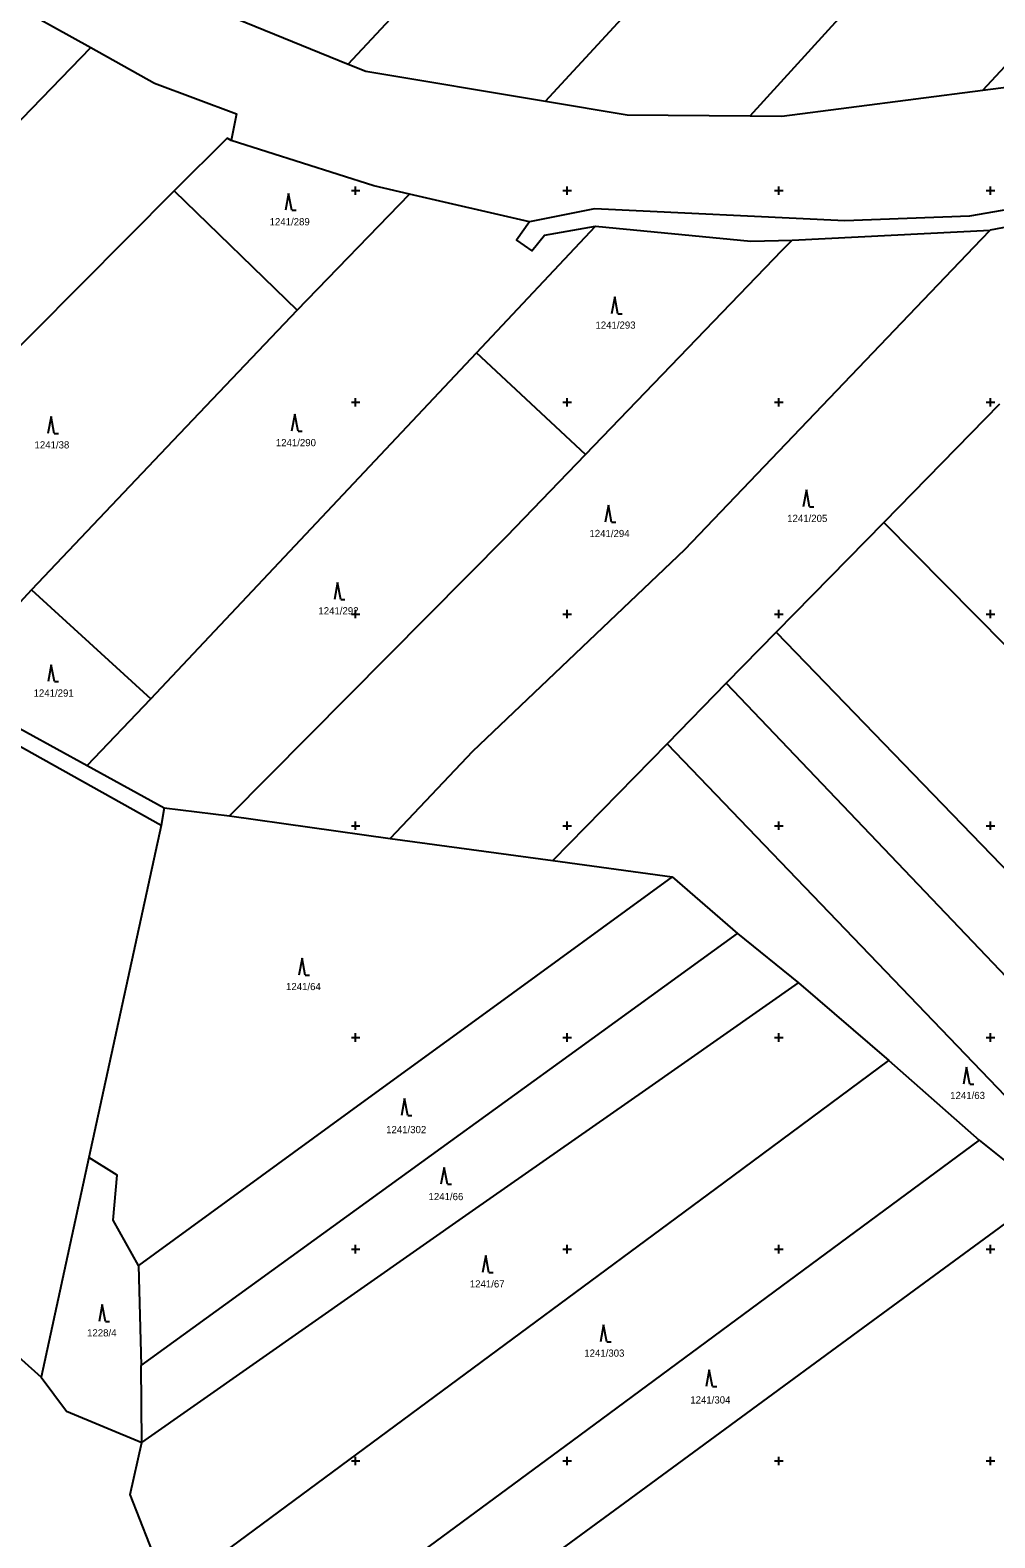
# Model space of a CAD drawing. Extents: x -776734 to -748832, y -1118122 to -976986.
# Drawn here: x -751976.9 to -751749, y -1115218.2 to -1114862.1 of the extents above; entities that cross this region are included whole.
import ezdxf

# ---------------------------------------------------------------- set-up
doc = ezdxf.new("R2010")
doc.units = 0
for name, color, linetype in [('KM_Hranice obce', 7, 'Continuous'), ('KM_Hranice parcel', 7, 'Continuous'), ('KM_Parcelní čísla', 7, 'Continuous'), ('KM_Značky kultur', 7, 'Continuous'), ('Level 61 Křížky', 7, 'Continuous')]:
    doc.layers.add(name, color=color, linetype=linetype)

msp = doc.modelspace()

# ---------------------------------------------------------------- linework, layer by layer
at = {"layer": 'KM_Hranice obce'}
for p, q in [((-751997.63, -1115016.98), (-751963.38, -1115035.78)), ((-751997.63, -1115016.98), (-751963.38, -1115035.78)), ((-751963.38, -1115035.78), (-751945.21, -1115045.76)), ((-751963.38, -1115035.78), (-751945.21, -1115045.76)), ((-751945.21, -1115045.76), (-751945.91, -1115049.96)), ((-751945.21, -1115045.76), (-751945.91, -1115049.96)), ((-751945.91, -1115049.96), (-751963.05, -1115128.37)), ((-751945.91, -1115049.96), (-751963.05, -1115128.37)), ((-751963.05, -1115128.37), (-751974.26, -1115180.24)), ((-751963.05, -1115128.37), (-751974.26, -1115180.24))]:
    msp.add_line(p, q, dxfattribs=at)
for points in [[(-751974.26, -1115180.24), (-751968.3, -1115188.26), (-751950.49, -1115195.65)], [(-751974.26, -1115180.24), (-751968.3, -1115188.26), (-751950.49, -1115195.65)], [(-751944.08, -1115231.19), (-751953.23, -1115207.95), (-751950.49, -1115195.65)], [(-751944.08, -1115231.19), (-751953.23, -1115207.95), (-751950.49, -1115195.65)]]:
    msp.add_lwpolyline(points, dxfattribs=at)
at = {"layer": 'KM_Hranice parcel'}
for p, q in [((-751939.11, -1114854.9), (-751901.76, -1114870.11)), ((-751942.86, -1114900.08), (-751913.81, -1114928.23)), ((-751913.81, -1114928.23), (-751887.29, -1114900.81)), ((-751858.89, -1114907.41), (-751887.29, -1114900.81)), ((-751871.43, -1114938.34), (-751843.29, -1114908.38)), ((-751796.89, -1114911.7), (-751750.07, -1114909.36)), ((-751845.67, -1114962.32), (-751871.43, -1114938.34)), ((-751747.89, -1114950.46), (-751775.23, -1114978.37)), ((-751775.23, -1114978.37), (-751800.61, -1115004.27)), ((-751976.59, -1114994.29), (-751997.63, -1115016.98)), ((-751976.59, -1114994.29), (-751948.36, -1115020.01)), ((-751800.61, -1115004.27), (-751812.42, -1115016.33)), ((-751812.42, -1115016.33), (-751826.42, -1115030.62)), ((-751963.38, -1115035.78), (-751948.36, -1115020.01)), ((-751826.42, -1115030.62), (-751853.43, -1115058.19)), ((-751945.21, -1115045.76), (-751929.77, -1115047.62)), ((-751929.77, -1115047.62), (-751891.86, -1115053)), ((-751891.86, -1115053), (-751853.43, -1115058.19)), ((-751853.43, -1115058.19), (-751825.21, -1115062.03)), ((-751825.21, -1115062.03), (-751809.77, -1115075.48)), ((-751809.77, -1115075.48), (-751795.37, -1115087.1)), ((-751795.37, -1115087.1), (-751774.05, -1115105.47)), ((-751774.05, -1115105.47), (-751752.68, -1115124.23)), ((-751752.68, -1115124.23), (-751736.94, -1115136.91)), ((-751950.49, -1115195.65), (-751872.35, -1115140.97)), ((-751951.27, -1115153.86), (-751950.66, -1115177.43)), ((-751950.49, -1115195.65), (-751950.66, -1115177.43))]:
    msp.add_line(p, q, dxfattribs=at)
for points in [[(-751901.76, -1114870.11), (-751882.74, -1114849.78), (-751856.57, -1114821.81), (-751816.46, -1114778.95), (-751734.46, -1114691.3), (-751678.34, -1114631.33), (-751649.12, -1114600.1), (-751642.03, -1114593.16)], [(-751855.14, -1114878.92), (-751824.7, -1114845.88), (-751783.59, -1114801.27), (-751766.66, -1114782.9), (-751738.11, -1114751.92), (-751722.27, -1114734.73), (-751704.16, -1114715.09), (-751657.73, -1114664.7), (-751615.2, -1114618.55), (-751610.82, -1114613.8)], [(-751806.78, -1114882.34), (-751721.42, -1114788.59), (-751667.32, -1114729.17), (-751615.76, -1114672.55), (-751613.29, -1114669.83)], [(-751751.78, -1114876.29), (-751714.18, -1114835.71), (-751676.85, -1114795.4), (-751615.92, -1114729.62)], [(-751995.98, -1114846.36), (-751983.87, -1114854.34), (-751962.52, -1114866.24)], [(-752071.79, -1114978.8), (-752018.24, -1114923.64), (-751962.52, -1114866.24)], [(-751962.52, -1114866.24), (-751947.48, -1114874.63), (-751928.13, -1114881.84), (-751929.4, -1114888.2)], [(-751619.58, -1114864.94), (-751671.94, -1114882.94), (-751717.81, -1114899.58), (-751754.97, -1114906.02), (-751784.43, -1114907.15), (-751843.55, -1114904.34), (-751858.89, -1114907.41)], [(-751751.78, -1114876.29), (-751711.61, -1114871.13), (-751698.88, -1114867.14)], [(-751901.76, -1114870.11), (-751897.6, -1114871.8), (-751855.14, -1114878.92)], [(-751806.78, -1114882.34), (-751799.31, -1114882.39), (-751751.78, -1114876.29)], [(-751855.14, -1114878.92), (-751835.87, -1114882.14), (-751806.78, -1114882.34)], [(-751929.4, -1114888.2), (-751930.34, -1114887.63), (-751942.86, -1114900.08)], [(-751887.29, -1114900.81), (-751895.7, -1114898.86), (-751929.4, -1114888.2)], [(-751694.2, -1114895.66), (-751707.54, -1114900.39), (-751716.28, -1114908.3), (-751720.75, -1114906.52), (-751718.97, -1114903.41), (-751750.07, -1114909.36)], [(-751942.86, -1114900.08), (-751987.35, -1114944.76), (-752031.68, -1114989.28)], [(-751945.91, -1115049.96), (-752018.39, -1115009.46), (-752037.33, -1114987.77), (-752047.6, -1114984.5), (-752062, -1114982.88), (-752081.53, -1114981.75), (-752107.58, -1114982.78), (-752126.36, -1114977.53), (-752161.17, -1114970.24), (-752199.76, -1114966.35), (-752226.58, -1114956.72), (-752268.96, -1114949.99), (-752281.26, -1114938.54), (-752287.32, -1114936.37), (-752294.09, -1114925.53), (-752295.5, -1114906.88)], [(-751750.07, -1114909.36), (-751752.2, -1114911.58), (-751822.31, -1114984.87), (-751872.35, -1115032.5), (-751891.86, -1115053)], [(-751858.89, -1114907.41), (-751861.96, -1114911.7), (-751858.34, -1114914.22), (-751855.35, -1114910.51), (-751843.29, -1114908.38)], [(-751843.29, -1114908.38), (-751806.64, -1114911.98), (-751796.89, -1114911.7)], [(-751845.67, -1114962.32), (-751799.21, -1114914.11), (-751796.89, -1114911.7)], [(-751913.81, -1114928.23), (-751944.63, -1114960.66), (-751976.59, -1114994.29)], [(-751948.36, -1115020.01), (-751915.5, -1114985.12), (-751871.43, -1114938.34)], [(-751929.77, -1115047.62), (-751864.28, -1114981.59), (-751845.67, -1114962.32)], [(-751775.23, -1114978.37), (-751717.58, -1115036.67), (-751682.94, -1115071.71), (-751652.82, -1115102.17)], [(-751800.61, -1115004.27), (-751745.16, -1115061.58), (-751698.78, -1115109.5), (-751666.74, -1115142.61)], [(-751812.42, -1115016.33), (-751759.07, -1115072.28), (-751706.35, -1115127.57), (-751675.46, -1115159.97)], [(-751826.42, -1115030.62), (-751774.79, -1115084.37), (-751714.53, -1115147.09), (-751684.11, -1115178.76)], [(-751825.21, -1115062.03), (-751868.43, -1115093.52), (-751897.79, -1115114.9), (-751951.27, -1115153.86)], [(-751950.66, -1115177.43), (-751882.07, -1115127.8), (-751847.27, -1115102.62), (-751809.77, -1115075.48)], [(-751872.35, -1115140.97), (-751831.43, -1115112.33), (-751795.37, -1115087.1)], [(-751944.08, -1115231.19), (-751862.87, -1115171.14), (-751813.03, -1115134.3), (-751774.05, -1115105.47)], [(-751752.68, -1115124.23), (-751792.47, -1115153.61), (-751848.81, -1115195.22), (-751887.16, -1115223.55)], [(-751951.27, -1115153.86), (-751957.26, -1115143.18), (-751956.35, -1115132.52), (-751963.05, -1115128.37)], [(-751879.71, -1115241.63), (-751837.58, -1115210.73), (-751780.06, -1115168.54), (-751736.94, -1115136.91)], [(-751998.68, -1115160.02), (-751991.34, -1115164.95), (-751974.26, -1115180.24)]]:
    msp.add_lwpolyline(points, dxfattribs=at)
at = {"layer": 'KM_Značky kultur'}
for p, q in [((-751915.82, -1114900.66), (-751916.57, -1114904.66)), ((-751915.07, -1114904.66), (-751915.82, -1114900.66)), ((-751915.07, -1114904.66), (-751914.074, -1114904.66)), ((-751838.78, -1114925.07), (-751839.53, -1114929.07)), ((-751838.03, -1114929.07), (-751838.78, -1114925.07)), ((-751838.03, -1114929.07), (-751837.034, -1114929.07)), ((-751914.35, -1114952.82), (-751915.1, -1114956.82)), ((-751913.6, -1114956.82), (-751914.35, -1114952.82)), ((-751971.95, -1114953.35), (-751972.7, -1114957.35)), ((-751971.2, -1114957.35), (-751971.95, -1114953.35)), ((-751971.2, -1114957.35), (-751970.204, -1114957.35)), ((-751913.6, -1114956.82), (-751912.604, -1114956.82)), ((-751793.5, -1114970.71), (-751794.25, -1114974.71)), ((-751792.75, -1114974.71), (-751793.5, -1114970.71)), ((-751840.28, -1114974.28), (-751841.03, -1114978.28)), ((-751839.53, -1114978.28), (-751840.28, -1114974.28)), ((-751792.75, -1114974.71), (-751791.754, -1114974.71)), ((-751839.53, -1114978.28), (-751838.534, -1114978.28)), ((-751904.25, -1114992.54), (-751905, -1114996.54)), ((-751903.5, -1114996.54), (-751904.25, -1114992.54)), ((-751903.5, -1114996.54), (-751902.504, -1114996.54)), ((-751971.91, -1115011.96), (-751972.66, -1115015.96)), ((-751971.16, -1115015.96), (-751971.91, -1115011.96)), ((-751971.16, -1115015.96), (-751970.164, -1115015.96)), ((-751912.63, -1115081.27), (-751913.38, -1115085.27)), ((-751911.88, -1115085.27), (-751912.63, -1115081.27)), ((-751911.88, -1115085.27), (-751910.884, -1115085.27)), ((-751755.65, -1115106.99), (-751756.4, -1115110.99)), ((-751754.9, -1115110.99), (-751755.65, -1115106.99)), ((-751754.9, -1115110.99), (-751753.904, -1115110.99)), ((-751888.43, -1115114.44), (-751889.18, -1115118.44)), ((-751887.68, -1115118.44), (-751888.43, -1115114.44)), ((-751887.68, -1115118.44), (-751886.684, -1115118.44)), ((-751879.07, -1115130.67), (-751879.82, -1115134.67)), ((-751878.32, -1115134.67), (-751879.07, -1115130.67)), ((-751878.32, -1115134.67), (-751877.324, -1115134.67)), ((-751869.25, -1115151.49), (-751870, -1115155.49)), ((-751868.5, -1115155.49), (-751869.25, -1115151.49)), ((-751868.5, -1115155.49), (-751867.504, -1115155.49)), ((-751959.85, -1115163.05), (-751960.6, -1115167.05)), ((-751959.1, -1115167.05), (-751959.85, -1115163.05)), ((-751959.1, -1115167.05), (-751958.104, -1115167.05)), ((-751841.39, -1115167.84), (-751842.14, -1115171.84)), ((-751840.64, -1115171.84), (-751841.39, -1115167.84)), ((-751840.64, -1115171.84), (-751839.644, -1115171.84)), ((-751816.43, -1115178.46), (-751817.18, -1115182.46)), ((-751815.68, -1115182.46), (-751816.43, -1115178.46)), ((-751815.68, -1115182.46), (-751814.684, -1115182.46))]:
    msp.add_line(p, q, dxfattribs=at)
at = {"layer": 'Level 61 Křížky'}
for p, q in [((-751900, -1114900), (-751900, -1114899)), ((-751850, -1114900), (-751850, -1114899)), ((-751800, -1114900), (-751800, -1114899)), ((-751750, -1114900), (-751750, -1114899)), ((-751901, -1114900), (-751899, -1114900)), ((-751900, -1114901), (-751900, -1114900)), ((-751851, -1114900), (-751849, -1114900)), ((-751850, -1114901), (-751850, -1114900)), ((-751801, -1114900), (-751799, -1114900)), ((-751800, -1114901), (-751800, -1114900)), ((-751751, -1114900), (-751749, -1114900)), ((-751750, -1114901), (-751750, -1114900)), ((-751900, -1114950), (-751900, -1114949)), ((-751850, -1114950), (-751850, -1114949)), ((-751800, -1114950), (-751800, -1114949)), ((-751750, -1114950), (-751750, -1114949)), ((-751901, -1114950), (-751899, -1114950)), ((-751900, -1114951), (-751900, -1114950)), ((-751851, -1114950), (-751849, -1114950)), ((-751850, -1114951), (-751850, -1114950)), ((-751801, -1114950), (-751799, -1114950)), ((-751800, -1114951), (-751800, -1114950)), ((-751751, -1114950), (-751749, -1114950)), ((-751750, -1114951), (-751750, -1114950)), ((-751900, -1115000), (-751900, -1114999)), ((-751850, -1115000), (-751850, -1114999)), ((-751800, -1115000), (-751800, -1114999)), ((-751750, -1115000), (-751750, -1114999)), ((-751901, -1115000), (-751899, -1115000)), ((-751900, -1115001), (-751900, -1115000)), ((-751851, -1115000), (-751849, -1115000)), ((-751850, -1115001), (-751850, -1115000)), ((-751801, -1115000), (-751799, -1115000)), ((-751800, -1115001), (-751800, -1115000)), ((-751751, -1115000), (-751749, -1115000)), ((-751750, -1115001), (-751750, -1115000)), ((-751900, -1115050), (-751900, -1115049)), ((-751850, -1115050), (-751850, -1115049)), ((-751800, -1115050), (-751800, -1115049)), ((-751750, -1115050), (-751750, -1115049)), ((-751901, -1115050), (-751899, -1115050)), ((-751900, -1115051), (-751900, -1115050)), ((-751851, -1115050), (-751849, -1115050)), ((-751850, -1115051), (-751850, -1115050)), ((-751801, -1115050), (-751799, -1115050)), ((-751800, -1115051), (-751800, -1115050)), ((-751751, -1115050), (-751749, -1115050)), ((-751750, -1115051), (-751750, -1115050)), ((-751901, -1115100), (-751899, -1115100)), ((-751900, -1115100), (-751900, -1115099)), ((-751900, -1115101), (-751900, -1115100)), ((-751851, -1115100), (-751849, -1115100)), ((-751850, -1115100), (-751850, -1115099)), ((-751850, -1115101), (-751850, -1115100)), ((-751801, -1115100), (-751799, -1115100)), ((-751800, -1115100), (-751800, -1115099)), ((-751800, -1115101), (-751800, -1115100)), ((-751751, -1115100), (-751749, -1115100)), ((-751750, -1115100), (-751750, -1115099)), ((-751750, -1115101), (-751750, -1115100)), ((-751901, -1115150), (-751899, -1115150)), ((-751900, -1115150), (-751900, -1115149)), ((-751900, -1115151), (-751900, -1115150)), ((-751851, -1115150), (-751849, -1115150)), ((-751850, -1115150), (-751850, -1115149)), ((-751850, -1115151), (-751850, -1115150)), ((-751801, -1115150), (-751799, -1115150)), ((-751800, -1115150), (-751800, -1115149)), ((-751800, -1115151), (-751800, -1115150)), ((-751751, -1115150), (-751749, -1115150)), ((-751750, -1115150), (-751750, -1115149)), ((-751750, -1115151), (-751750, -1115150)), ((-751901, -1115200), (-751899, -1115200)), ((-751900, -1115200), (-751900, -1115199)), ((-751900, -1115201), (-751900, -1115200)), ((-751851, -1115200), (-751849, -1115200)), ((-751850, -1115200), (-751850, -1115199)), ((-751850, -1115201), (-751850, -1115200)), ((-751801, -1115200), (-751799, -1115200)), ((-751800, -1115200), (-751800, -1115199)), ((-751800, -1115201), (-751800, -1115200)), ((-751751, -1115200), (-751749, -1115200)), ((-751750, -1115200), (-751750, -1115199)), ((-751750, -1115201), (-751750, -1115200))]:
    msp.add_line(p, q, dxfattribs=at)

# ---------------------------------------------------------------- texts
at = {"layer": 'KM_Parcelní čísla'}
for s, p in [('1241/289', (-751920.31, -1114908.21)), ('1241/293', (-751843.33, -1114932.62)), ('1241/38', (-751975.85, -1114960.9)), ('1241/290', (-751918.84, -1114960.37)), ('1241/205', (-751798.03, -1114978.26)), ('1241/294', (-751844.75, -1114981.83)), ('1241/292', (-751908.78, -1115000.09)), ('1241/291', (-751976.07, -1115019.51)), ('1241/64', (-751916.43, -1115088.82)), ('1241/63', (-751759.52, -1115114.54)), ('1241/302', (-751892.78, -1115122.6)), ('1241/66', (-751882.76, -1115138.42)), ('1241/67', (-751873.01, -1115159.04)), ('1228/4', (-751963.43, -1115170.6)), ('1241/303', (-751845.97, -1115175.39)), ('1241/304', (-751820.92, -1115186.44))]:
    msp.add_text(s, height=1.7, dxfattribs=at).set_placement(p)

doc.saveas('drawing.dxf')
